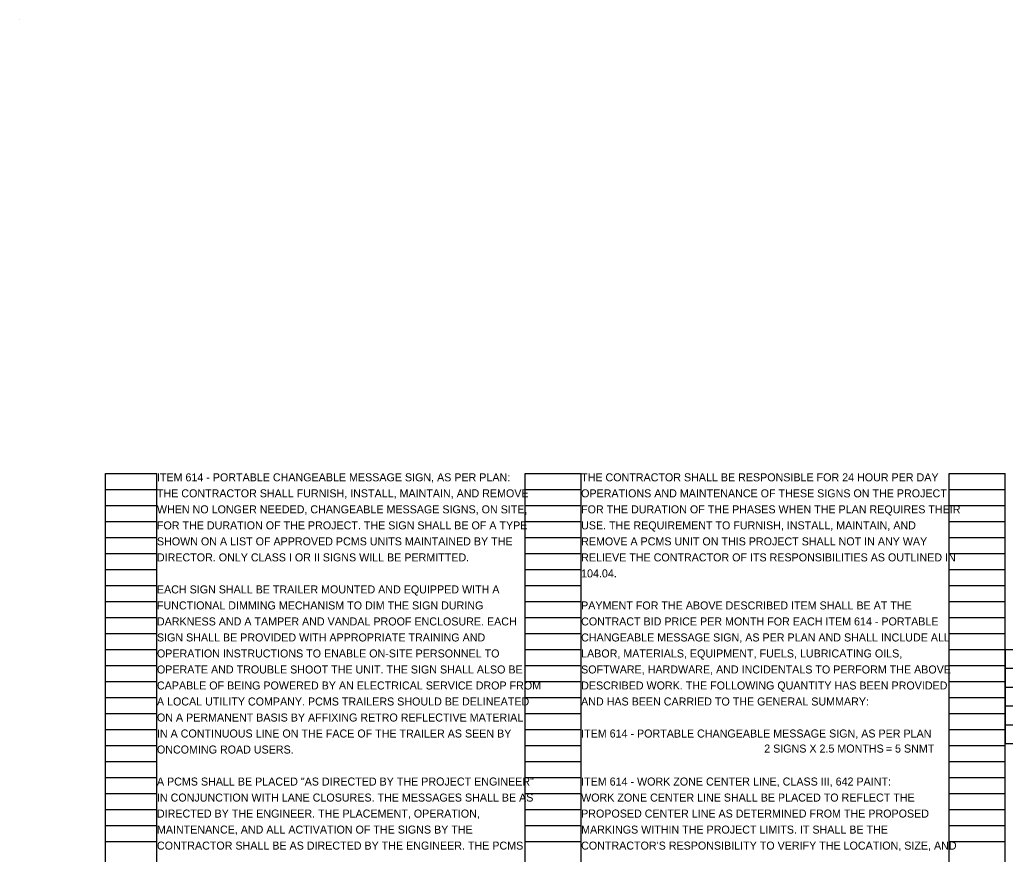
# Model space of a CAD drawing. Extents: x 24172 to 24226.9, y 11011.9 to 11091.2.
# Drawn here: x 24194.95 to 24212.19, y 11026.37 to 11040.97 of the extents above; entities that cross this region are included whole.
import ezdxf

# ---------------------------------------------------------------- set-up
doc = ezdxf.new("R2010")
doc.units = 0
doc.layers.add('SC_Scratch1', color=7, linetype='Continuous')
doc.layers.add('SH_Data', color=7, linetype='Continuous')

msp = doc.modelspace()

# ---------------------------------------------------------------- linework, layer by layer
at = {"layer": 'SH_Data'}
for p, q in [((24194.95, 11040.967), (24194.95, 11040.967)), ((24196.45, 11012.874), (24196.45, 11033.034)), ((24196.45, 11033.034), (24197.35, 11033.034)), ((24197.35, 11012.874), (24197.35, 11033.034)), ((24203.79, 11012.874), (24203.79, 11033.034)), ((24203.79, 11033.034), (24204.77, 11033.034)), ((24204.77, 11012.874), (24204.77, 11033.034)), ((24211.21, 11012.874), (24211.21, 11033.034)), ((24211.21, 11033.034), (24212.19, 11033.034)), ((24212.19, 11012.874), (24212.19, 11033.034)), ((24196.45, 11032.754), (24197.35, 11032.754)), ((24203.79, 11032.754), (24204.77, 11032.754)), ((24211.21, 11032.754), (24212.19, 11032.754)), ((24196.45, 11032.474), (24197.35, 11032.474)), ((24203.79, 11032.474), (24204.77, 11032.474)), ((24211.21, 11032.474), (24212.19, 11032.474)), ((24196.45, 11032.194), (24197.35, 11032.194)), ((24203.79, 11032.194), (24204.77, 11032.194)), ((24211.21, 11032.194), (24212.19, 11032.194)), ((24196.45, 11031.914), (24197.35, 11031.914)), ((24203.79, 11031.914), (24204.77, 11031.914)), ((24211.21, 11031.914), (24212.19, 11031.914)), ((24196.45, 11031.634), (24197.35, 11031.634)), ((24203.79, 11031.634), (24204.77, 11031.634)), ((24211.21, 11031.634), (24212.19, 11031.634)), ((24196.45, 11031.354), (24197.35, 11031.354)), ((24203.79, 11031.354), (24204.77, 11031.354)), ((24211.21, 11031.354), (24212.19, 11031.354)), ((24196.45, 11031.074), (24197.35, 11031.074)), ((24203.79, 11031.074), (24204.77, 11031.074)), ((24211.21, 11031.074), (24212.19, 11031.074)), ((24196.45, 11030.794), (24197.35, 11030.794)), ((24203.79, 11030.794), (24204.77, 11030.794)), ((24211.21, 11030.794), (24212.19, 11030.794)), ((24196.45, 11030.514), (24197.35, 11030.514)), ((24203.79, 11030.514), (24204.77, 11030.514)), ((24211.21, 11030.514), (24212.19, 11030.514)), ((24196.45, 11030.234), (24197.35, 11030.234)), ((24203.79, 11030.234), (24204.77, 11030.234)), ((24211.21, 11030.234), (24212.19, 11030.234)), ((24196.45, 11029.954), (24197.35, 11029.954)), ((24203.79, 11029.954), (24204.77, 11029.954)), ((24211.21, 11029.954), (24212.19, 11029.954)), ((24212.19, 11029.954), (24216.851, 11029.954)), ((24212.19, 11029.954), (24212.19, 11028.307)), ((24196.45, 11029.674), (24197.35, 11029.674)), ((24203.79, 11029.674), (24204.77, 11029.674)), ((24211.21, 11029.674), (24212.19, 11029.674)), ((24212.19, 11029.625), (24216.851, 11029.625)), ((24196.45, 11029.394), (24197.35, 11029.394)), ((24203.79, 11029.394), (24204.77, 11029.394)), ((24211.21, 11029.394), (24212.19, 11029.394)), ((24212.19, 11029.295), (24216.851, 11029.295)), ((24196.45, 11029.114), (24197.35, 11029.114)), ((24203.79, 11029.114), (24204.77, 11029.114)), ((24211.21, 11029.114), (24212.19, 11029.114)), ((24212.19, 11028.966), (24216.851, 11028.966)), ((24196.45, 11028.834), (24197.35, 11028.834)), ((24203.79, 11028.834), (24204.77, 11028.834)), ((24211.21, 11028.834), (24212.19, 11028.834)), ((24196.45, 11028.554), (24197.35, 11028.554)), ((24203.79, 11028.554), (24204.77, 11028.554)), ((24211.21, 11028.554), (24212.19, 11028.554)), ((24212.19, 11028.636), (24216.851, 11028.636)), ((24196.45, 11028.274), (24197.35, 11028.274)), ((24203.79, 11028.274), (24204.77, 11028.274)), ((24211.21, 11028.274), (24212.19, 11028.274)), ((24212.19, 11028.307), (24216.851, 11028.307)), ((24196.45, 11027.994), (24197.35, 11027.994)), ((24203.79, 11027.994), (24204.77, 11027.994)), ((24211.21, 11027.994), (24212.19, 11027.994)), ((24196.45, 11027.714), (24197.35, 11027.714)), ((24203.79, 11027.714), (24204.77, 11027.714)), ((24211.21, 11027.714), (24212.19, 11027.714)), ((24196.45, 11027.434), (24197.35, 11027.434)), ((24203.79, 11027.434), (24204.77, 11027.434)), ((24211.21, 11027.434), (24212.19, 11027.434)), ((24196.45, 11027.154), (24197.35, 11027.154)), ((24203.79, 11027.154), (24204.77, 11027.154)), ((24211.21, 11027.154), (24212.19, 11027.154)), ((24196.45, 11026.874), (24197.35, 11026.874)), ((24203.79, 11026.874), (24204.77, 11026.874)), ((24211.21, 11026.874), (24212.19, 11026.874)), ((24196.45, 11026.594), (24197.35, 11026.594)), ((24203.79, 11026.594), (24204.77, 11026.594)), ((24211.21, 11026.594), (24212.19, 11026.594))]:
    msp.add_line(p, q, dxfattribs=at)

# ---------------------------------------------------------------- texts
at = {"layer": 'SC_Scratch1'}
for s, p in [('ITEM 614 - PORTABLE CHANGEABLE MESSAGE SIGN, AS PER PLAN:', (24197.35, 11032.894)), ('THE CONTRACTOR SHALL BE RESPONSIBLE FOR 24 HOUR PER DAY ', (24204.77, 11032.894)), ('THE CONTRACTOR SHALL FURNISH, INSTALL, MAINTAIN, AND REMOVE ', (24197.35, 11032.614)), ('OPERATIONS AND MAINTENANCE OF THESE SIGNS ON THE PROJECT ', (24204.77, 11032.614)), ('WHEN NO LONGER NEEDED, CHANGEABLE MESSAGE SIGNS, ON SITE, ', (24197.35, 11032.334)), ('FOR THE DURATION OF THE PHASES WHEN THE PLAN REQUIRES THEIR ', (24204.77, 11032.334)), ('FOR THE DURATION OF THE PROJECT. THE SIGN SHALL BE OF A TYPE ', (24197.35, 11032.054)), ('USE. THE REQUIREMENT TO FURNISH, INSTALL, MAINTAIN, AND ', (24204.77, 11032.054)), ('SHOWN ON A LIST OF APPROVED PCMS UNITS MAINTAINED BY THE ', (24197.35, 11031.774)), ('REMOVE A PCMS UNIT ON THIS PROJECT SHALL NOT IN ANY WAY ', (24204.77, 11031.774)), ('DIRECTOR. ONLY CLASS I OR II SIGNS WILL BE PERMITTED.', (24197.35, 11031.494)), ('RELIEVE THE CONTRACTOR OF ITS RESPONSIBILITIES AS OUTLINED IN ', (24204.77, 11031.494)), ('104.04.', (24204.77, 11031.214)), ('EACH SIGN SHALL BE TRAILER MOUNTED AND EQUIPPED WITH A ', (24197.35, 11030.934)), ('FUNCTIONAL DIMMING MECHANISM TO DIM THE SIGN DURING ', (24197.35, 11030.654)), ('PAYMENT FOR THE ABOVE DESCRIBED ITEM SHALL BE AT THE ', (24204.77, 11030.654)), ('DARKNESS AND A TAMPER AND VANDAL PROOF ENCLOSURE. EACH ', (24197.35, 11030.374)), ('CONTRACT BID PRICE PER MONTH FOR EACH ITEM 614 - PORTABLE ', (24204.77, 11030.374)), ('SIGN SHALL BE PROVIDED WITH APPROPRIATE TRAINING AND ', (24197.35, 11030.094)), ('CHANGEABLE MESSAGE SIGN, AS PER PLAN AND SHALL INCLUDE ALL ', (24204.77, 11030.094)), ('OPERATION INSTRUCTIONS TO ENABLE ON-SITE PERSONNEL TO ', (24197.35, 11029.814)), ('LABOR, MATERIALS, EQUIPMENT, FUELS, LUBRICATING OILS, ', (24204.77, 11029.814)), ('OPERATE AND TROUBLE SHOOT THE UNIT. THE SIGN SHALL ALSO BE ', (24197.35, 11029.534)), ('SOFTWARE, HARDWARE, AND INCIDENTALS TO PERFORM THE ABOVE ', (24204.77, 11029.534)), ('CAPABLE OF BEING POWERED BY AN ELECTRICAL SERVICE DROP FROM ', (24197.35, 11029.254)), ('DESCRIBED WORK. THE FOLLOWING QUANTITY HAS BEEN PROVIDED ', (24204.77, 11029.254)), ('A LOCAL UTILITY COMPANY. PCMS TRAILERS SHOULD BE DELINEATED ', (24197.35, 11028.974)), ('AND HAS BEEN CARRIED TO THE GENERAL SUMMARY:', (24204.77, 11028.974)), ('ON A PERMANENT BASIS BY AFFIXING RETRO REFLECTIVE MATERIAL, ', (24197.35, 11028.694)), ('IN A CONTINUOUS LINE ON THE FACE OF THE TRAILER AS SEEN BY ', (24197.35, 11028.414)), ('ITEM 614 - PORTABLE CHANGEABLE MESSAGE SIGN, AS PER PLAN', (24204.77, 11028.414)), ('ONCOMING ROAD USERS.', (24197.35, 11028.134)), ('2 SIGNS X 2.5 MONTHS', (24207.973, 11028.151)), ('= 5 SNMT', (24210.1, 11028.151)), ('A PCMS SHALL BE PLACED "AS DIRECTED BY THE PROJECT ENGINEER" ', (24197.35, 11027.574)), ('ITEM 614 - WORK ZONE CENTER LINE, CLASS III, 642 PAINT:', (24204.77, 11027.574)), ('IN CONJUNCTION WITH LANE CLOSURES. THE MESSAGES SHALL BE AS ', (24197.35, 11027.294)), ('WORK ZONE CENTER LINE SHALL BE PLACED TO REFLECT THE ', (24204.77, 11027.294)), ('DIRECTED BY THE ENGINEER. THE PLACEMENT, OPERATION, ', (24197.35, 11027.014)), ('PROPOSED CENTER LINE AS DETERMINED FROM THE PROPOSED ', (24204.77, 11027.014)), ('MAINTENANCE, AND ALL ACTIVATION OF THE SIGNS BY THE ', (24197.35, 11026.734)), ('MARKINGS WITHIN THE PROJECT LIMITS. IT SHALL BE THE ', (24204.77, 11026.734)), ('CONTRACTOR SHALL BE AS DIRECTED BY THE ENGINEER. THE PCMS ', (24197.35, 11026.454)), ("CONTRACTOR'S RESPONSIBILITY TO VERIFY THE LOCATION, SIZE, AND ", (24204.77, 11026.454))]:
    msp.add_text(s, height=0.14, dxfattribs=at).set_placement(p)

doc.saveas('drawing.dxf')
